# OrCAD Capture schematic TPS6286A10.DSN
size D; title: TPS6286A10: 10A Synchronous Step Down Converter; rev: 1.0; note: Datasheet: SLUSFG2C    EVM: SLUUD28; note: Synchronous Step Down Converter
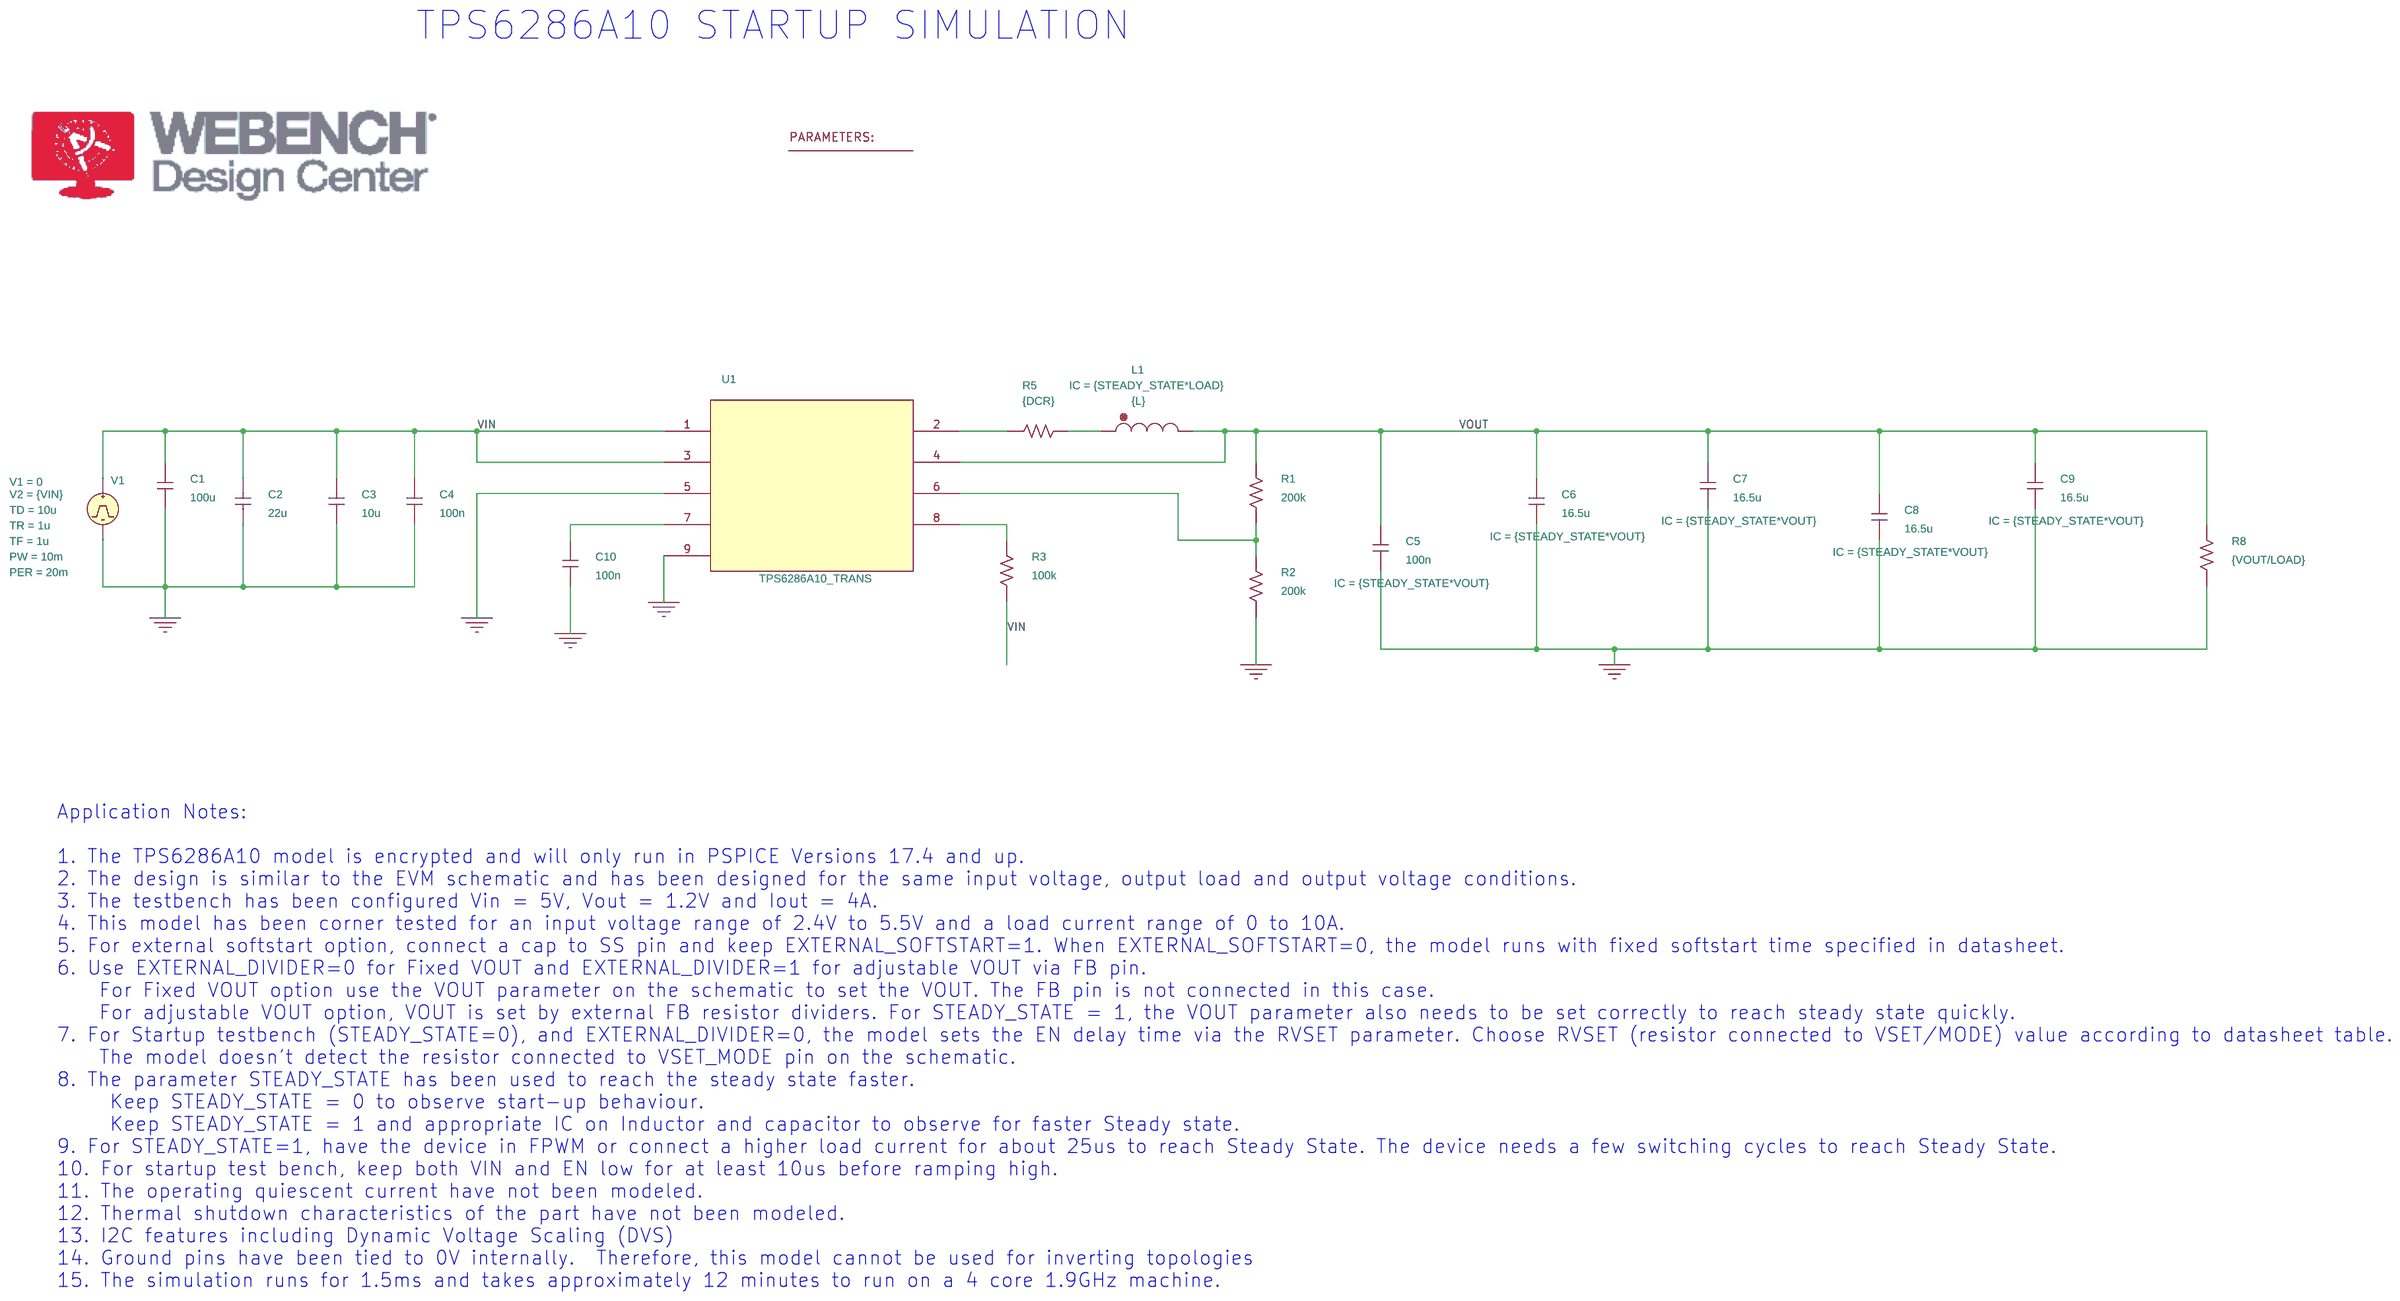
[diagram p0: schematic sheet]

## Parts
1  PARAM
C1  100u  [cap196]
C2  22u  [cap196]
C3  10u  [cap196]
C4  100n  [cap196]
C5  100n  [RAD/CK05]
C6  16.5u  [RAD/CK05]
C7  16.5u  [RAD/CK05]
C8  16.5u  [RAD/CK05]
C9  16.5u  [RAD/CK05]
C10  100n  [cap196]
L1  {L}  [DISC350x175LS200x100034]
R1  200k  [AXRC05]
R2  200k  [AXRC05]
R3  100k  [AXRC05]
R5  {DCR}  [AXRC05]
R8  {VOUT/LOAD}  [AXRC05]
U1  TPS6286A10_TRANS
V1  VPULSE

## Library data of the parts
1 = PARAM: DCR: 5m; EXTERNAL_SOFTSTART: 0; L: 470n; LOAD: 4; RVSET: 56.2k; STEADY_STATE: 0; VIN: 5; VOUT: 1.2
C1-C4 C10 = C
C5 = C: AppProp: InductiveSlave:;SRF:;PrevCap:100n;PrevESL:; IC: {STEADY_STATE*VOUT}
C6-C9 = C: AppProp: InductiveSlave:SRF;SRF:1.7940e+6;PrevCap:16.5u;PrevESL:477p; ESL: 477p; ESR: 2m; IC: {STEADY_STATE*VOUT}
L1 = L: IC: {STEADY_STATE*LOAD}
R1-R3 R5 R8 = R
U1 = TPS6286A10
V1 = VPULSE: PER: 20m; PW: 10m; TD: 10u; TF: 1u; TR: 1u; V1: 0; V2: {VIN}

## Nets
VIN: C1.2 C2.2 C3.2 C4.2 R3.1 U1.1(VIN) U1.3(EN) V1.1(+)
0: C1.1 C2.1 C3.1 C4.1 C5.2 C6.2 C7.2 C8.2 C9.2 C10.1 R2.1 R8.1 U1.5(VSET_MODE) U1.9(GND) V1.2(-)
VOUT: C5.1 C6.1 C7.1 C8.1 C9.1 L1.2 R1.2 R8.2 U1.4(OUT)
N16777492: R5.1 U1.2(SW)
N16777495: L1.1 R5.2
N16777557: R3.2 U1.8(PG)
N16778058: C10.2 U1.7(SS)
N16780726: R1.1 R2.2 U1.6(FB)

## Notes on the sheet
- TPS6286A10 STARTUP SIMULATION
- Application Notes:
  1. The TPS6286A10 model is encrypted and will only run in PSPICE Versions 17.4 and up.
  2. The design is similar to the EVM schematic and has been designed for the same input voltage, output load and output voltage conditions.
  3. The testbench has been configured Vin = 5V, Vout = 1.2V and Iout = 4A.
  4. This model has been corner tested for an input voltage range of 2.4V to 5.5V and a load current range of 0 to 10A.
  5. For external softstart option, connect a cap to SS pin and keep EXTERNAL_SOFTSTART=1. When EXTERNAL_SOFTSTART=0, the model runs with fixed softstart time specified in datasheet.
  6. Use EXTERNAL_DIVIDER=0 for Fixed VOUT and EXTERNAL_DIVIDER=1 for adjustable VOUT via FB pin.
      For Fixed VOUT option use the VOUT parameter on the schematic to set the VOUT. The FB pin is not connected in this case.
      For adjustable VOUT option, VOUT is set by external FB resistor dividers. For STEADY_STATE = 1, the VOUT parameter also needs to be set correctly to reach steady state quickly.
  7. For Startup testbench (STEADY_STATE=0), and EXTERNAL_DIVIDER=0, the model sets the EN delay time via the RVSET parameter. Choose RVSET (resistor connected to VSET/MODE) value according to datasheet table.
      The model doesn't detect the resistor connected to VSET_MODE pin on the schematic.
  8. The parameter STEADY_STATE has been used to reach the steady state faster.
       Keep STEADY_STATE = 0 to observe start-up behaviour.
       Keep STEADY_STATE = 1 and appropriate IC on Inductor and capacitor to observe for faster Steady state.
  9. For STEADY_STATE=1, have the device in FPWM or connect a higher load current for about 25us to reach Steady State. The device needs a few switching cycles to reach Steady State.
  10. For startup test bench, keep both VIN and EN low for at least 10us before ramping high.
  11. The operating quiescent current have not been modeled.
  12. Thermal shutdown characteristics of the part have not been modeled.
  13. I2C features including Dynamic Voltage Scaling (DVS)
  14. Ground pins have been tied to 0V internally.  Therefore, this model cannot be used for inverting topologies
  15. The simulation runs for 1.5ms and takes approximately 12 minutes to run on a 4 core 1.9GHz machine.
